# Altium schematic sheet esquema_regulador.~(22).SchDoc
size A4
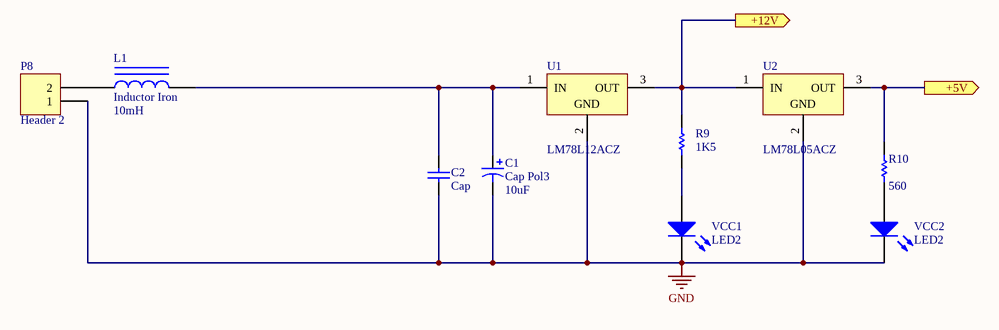
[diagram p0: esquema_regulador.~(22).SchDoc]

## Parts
C1  Cap Pol3  value 10uF  [CAPPR3.5-8X15]
C2  Cap  [RAD-0.1]
L1  Inductor Iron  value 10mH  [bobina_Choque]
P8  Header 2  [pwheader1x2]
R9  value 1K5  [AXIAL-0.3]  (hidden comment: Carbon 1/8w 5%)
R10  value 560  [AXIAL-0.3]  (hidden comment: Carbon 1/8w 5%)
U1  LM78L12ACZ  [T03B]
U2  LM78L05ACZ  [T03B]
VCC1  LED2  [CAPPR2.5-6.3X5]
VCC2  LED2  [CAPPR2.5-6.3X5]

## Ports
+5V (out), +12V (out)

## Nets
GND: C1.2 C2.1 P8.1 U1.2(GND) U2.2(GND) VCC1.2(K) VCC2.2(K)
+5V: R10.2 U2.3(OUT) ; port +5V
+12V: R9.2 U1.3(OUT) U2.1(IN) ; port +12V
NetC1_1: C1.1 C2.2 L1.2 U1.1(IN)
NetL1_1: L1.1 P8.2
NetR9_1: R9.1 VCC1.1(A)
NetR10_1: R10.1 VCC2.1(A)

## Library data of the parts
C1 = Cap Pol3: Polarized Capacitor 35V
C2 = Cap: Capacitor
L1 = Inductor Iron: Magnetic-Core Inductor
P8 = Header 2: Header, 2-Pin
R9 R10 = Res Semi: Semiconductor Resistor
U1 = LM78L12ACZ: 3-Terminal Positive Regulator; PackageDocument: 2000
U2 = LM78L05ACZ: 3-Terminal Positive Regulator; PackageDocument: 2000
VCC1 VCC2 = LED2: Typical RED, GREEN, YELLOW, AMBER GaAs LED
